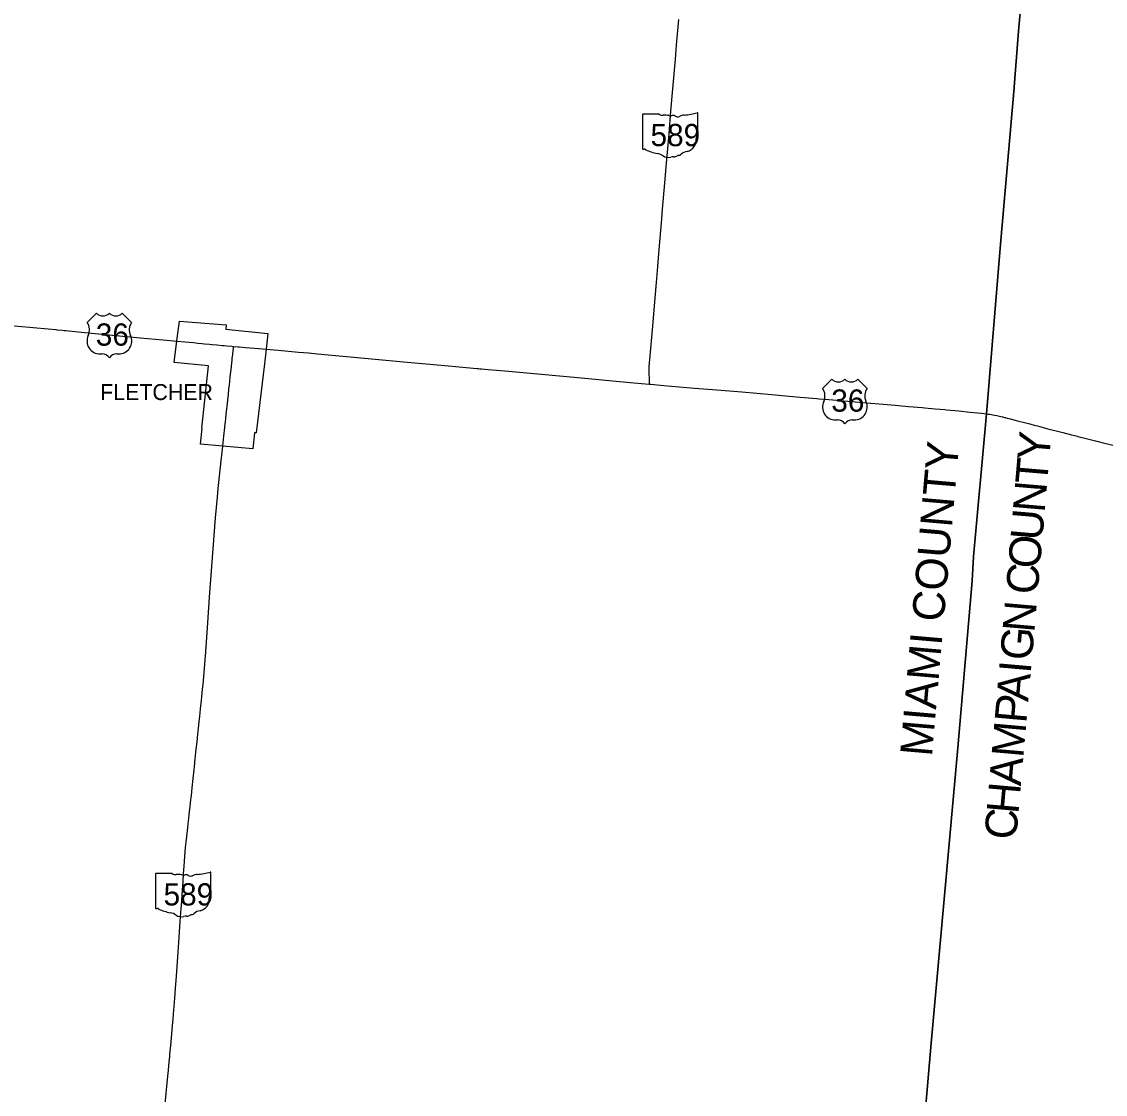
# Model space of a CAD drawing. Extents: x 0 to 34, y 0 to 22.
# Drawn here: x 5.598 to 6.143, y 17.041 to 17.581 of the extents above; entities that cross this region are included whole.
import ezdxf

# ---------------------------------------------------------------- set-up
doc = ezdxf.new("R2010")
doc.units = 0
for name, color, linetype in [('GM_X_Corporation', 7, 'Continuous'), ('GM_X_Corporation_Text', 7, 'Continuous'), ('GM_X_County', 7, 'Continuous'), ('GM_X_County_Text', 7, 'Continuous'), ('GM_X_State_Location', 7, 'Continuous'), ('GM_X_State_Route', 7, 'Continuous'), ('GM_X_State_Shield', 7, 'Continuous'), ('GM_X_US_Location', 7, 'Continuous'), ('GM_X_US_Route', 7, 'Continuous'), ('GM_X_US_Shield', 7, 'Continuous')]:
    doc.layers.add(name, color=color, linetype=linetype)

msp = doc.modelspace()

# ---------------------------------------------------------------- linework, layer by layer
at = {"layer": 'GM_X_Corporation'}
msp.add_lwpolyline([(5.700850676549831, 17.428726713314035), (5.700656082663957, 17.42652761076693), (5.721836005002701, 17.424479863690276), (5.7210201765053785, 17.416544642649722), (5.720108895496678, 17.409158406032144), (5.71590265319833, 17.374392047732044), (5.715172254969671, 17.3744505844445), (5.714276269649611, 17.36640989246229), (5.699149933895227, 17.36769823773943), (5.687913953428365, 17.368721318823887), (5.688787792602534, 17.376755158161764), (5.688580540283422, 17.376775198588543), (5.691884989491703, 17.408043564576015), (5.674607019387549, 17.40982499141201), (5.676057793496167, 17.42065648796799), (5.677288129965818, 17.43055507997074)], close=True, dxfattribs=at)
at = {"layer": 'GM_X_County'}
for points in [[(6.105406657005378, 17.639886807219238), (6.099635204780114, 17.576585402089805), (6.097431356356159, 17.546236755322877), (6.090612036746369, 17.469472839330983), (6.083568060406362, 17.384004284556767), (6.077029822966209, 17.312128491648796), (6.076320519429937, 17.299830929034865), (6.0692306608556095, 17.21568499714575), (6.055752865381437, 17.06702314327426), (6.043257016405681, 16.922665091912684)], [(6.043257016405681, 16.922665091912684), (6.055752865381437, 17.06702314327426), (6.0692306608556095, 17.21568499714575), (6.076320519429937, 17.299830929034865), (6.077029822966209, 17.312128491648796), (6.083568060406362, 17.384004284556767), (6.090612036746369, 17.469472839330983), (6.097431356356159, 17.546236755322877), (6.099635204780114, 17.576585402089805), (6.105406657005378, 17.639886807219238)]]:
    msp.add_lwpolyline(points, dxfattribs=at)
at = {"layer": 'GM_X_State_Route'}
for p, q in [((5.707579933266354, 17.417657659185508), (5.710583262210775, 17.417391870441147)), ((5.742324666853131, 17.414603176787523), (5.74691799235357, 17.414161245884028))]:
    msp.add_line(p, q, dxfattribs=at)
for points in [[(5.913807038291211, 17.39895686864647), (5.913881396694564, 17.399477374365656), (5.913944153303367, 17.400251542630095), (5.913972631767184, 17.400878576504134), (5.913959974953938, 17.401612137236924), (5.913806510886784, 17.404296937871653), (5.913774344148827, 17.405406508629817), (5.9137875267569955, 17.406411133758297), (5.9138497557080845, 17.40773059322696), (5.914282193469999, 17.413198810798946), (5.915440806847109, 17.426329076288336), (5.916977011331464, 17.44413862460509), (5.917491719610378, 17.450036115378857), (5.91811506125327, 17.458116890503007), (5.918688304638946, 17.464735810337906), (5.919180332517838, 17.470323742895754), (5.920293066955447, 17.48416172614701), (5.920362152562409, 17.48501974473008), (5.921729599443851, 17.500356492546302), (5.922553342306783, 17.510178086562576), (5.923814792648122, 17.52493948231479), (5.924765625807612, 17.536341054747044), (5.925725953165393, 17.54763715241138), (5.926969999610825, 17.562507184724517), (5.9275849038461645, 17.56954061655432), (5.927593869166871, 17.56964239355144), (5.928712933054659, 17.582573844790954)], [(5.699173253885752, 17.36768534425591), (5.699720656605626, 17.372706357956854), (5.700169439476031, 17.37705024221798), (5.700243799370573, 17.377766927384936), (5.700327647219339, 17.37857695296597), (5.700496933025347, 17.380098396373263), (5.700653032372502, 17.381504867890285), (5.700699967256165, 17.38192833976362), (5.7010395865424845, 17.385109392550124), (5.7013280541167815, 17.38780895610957), (5.701644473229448, 17.390772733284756), (5.70196088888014, 17.393612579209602), (5.702281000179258, 17.396586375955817), (5.702492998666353, 17.39847116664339), (5.702693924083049, 17.400348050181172), (5.702919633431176, 17.402453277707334), (5.703224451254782, 17.405280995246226), (5.703309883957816, 17.40611792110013), (5.703509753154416, 17.407915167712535), (5.7038578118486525, 17.411044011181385), (5.703962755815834, 17.411992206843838), (5.7041436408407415, 17.413622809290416), (5.704223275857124, 17.41434476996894), (5.70449855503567, 17.416909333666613), (5.704602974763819, 17.417903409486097)], [(5.704602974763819, 17.417903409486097), (5.7069360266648, 17.417714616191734), (5.707579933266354, 17.417657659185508)], [(5.710583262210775, 17.417391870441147), (5.715243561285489, 17.416979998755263), (5.721039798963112, 17.416499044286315)], [(5.721039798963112, 17.416499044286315), (5.727116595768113, 17.415981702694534), (5.737265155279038, 17.415042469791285), (5.742324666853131, 17.414603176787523)], [(5.74691799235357, 17.414161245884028), (5.752141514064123, 17.413658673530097), (5.7632203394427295, 17.412667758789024), (5.775805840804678, 17.411523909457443), (5.790079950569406, 17.410212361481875), (5.812725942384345, 17.4081329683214), (5.826985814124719, 17.406835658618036), (5.827646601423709, 17.40677870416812)], [(5.827646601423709, 17.40677870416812), (5.828627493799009, 17.406693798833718), (5.829464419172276, 17.406621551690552)], [(5.829464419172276, 17.406621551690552), (5.8328042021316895, 17.406333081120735), (5.841157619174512, 17.405588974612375), (5.855948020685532, 17.4042869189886), (5.870533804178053, 17.402873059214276), (5.8831936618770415, 17.401663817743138), (5.89537045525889, 17.400584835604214), (5.906141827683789, 17.39962661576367), (5.913807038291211, 17.39895686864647)], [(5.689470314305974, 17.249522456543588), (5.689642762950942, 17.25165827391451), (5.690598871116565, 17.264126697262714), (5.691658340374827, 17.278693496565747), (5.692547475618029, 17.291634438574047), (5.693166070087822, 17.300576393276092), (5.694280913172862, 17.315985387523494), (5.695422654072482, 17.33155311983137), (5.696447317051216, 17.341997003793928), (5.696871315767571, 17.346409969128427), (5.698088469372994, 17.357306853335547), (5.699173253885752, 17.36768534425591)], [(5.6702084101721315, 17.03636264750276), (5.670733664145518, 17.041926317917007), (5.671039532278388, 17.045287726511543), (5.671543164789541, 17.050376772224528), (5.671832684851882, 17.05346816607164), (5.6722271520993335, 17.0576749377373), (5.6724491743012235, 17.060144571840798), (5.672571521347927, 17.061562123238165), (5.672990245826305, 17.065918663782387), (5.673886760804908, 17.075738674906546), (5.674199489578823, 17.079364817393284), (5.674409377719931, 17.081674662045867), (5.674580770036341, 17.08367283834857), (5.675003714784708, 17.089670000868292), (5.675394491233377, 17.094823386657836), (5.675666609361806, 17.098609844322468), (5.676149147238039, 17.105501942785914), (5.6766659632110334, 17.112969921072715), (5.677013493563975, 17.117701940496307), (5.67739372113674, 17.123172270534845), (5.677702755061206, 17.12806671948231), (5.677881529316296, 17.130775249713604), (5.678314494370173, 17.136534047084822), (5.67846584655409, 17.13869095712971), (5.678679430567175, 17.14158353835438), (5.6788555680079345, 17.144161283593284), (5.67914930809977, 17.148210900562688), (5.679451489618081, 17.152416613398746), (5.679712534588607, 17.156151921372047), (5.679912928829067, 17.15878029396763), (5.68009223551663, 17.161199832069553), (5.6804582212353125, 17.1655331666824), (5.680712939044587, 17.16828863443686), (5.681000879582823, 17.171121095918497), (5.6815182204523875, 17.1756785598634), (5.681718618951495, 17.177469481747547), (5.6820466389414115, 17.18026028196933), (5.682269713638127, 17.182206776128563), (5.6827300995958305, 17.186364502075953), (5.683072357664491, 17.189629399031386), (5.683330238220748, 17.191680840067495), (5.683777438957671, 17.195639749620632), (5.684293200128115, 17.200310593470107), (5.68472616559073, 17.2046602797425), (5.684893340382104, 17.206445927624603), (5.685311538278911, 17.21016857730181), (5.6856680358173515, 17.21357428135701), (5.6858357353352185, 17.21514792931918), (5.686232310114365, 17.218805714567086), (5.686628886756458, 17.22259428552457), (5.686802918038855, 17.224325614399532), (5.68695110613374, 17.225741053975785), (5.687308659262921, 17.228936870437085), (5.687599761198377, 17.231732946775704), (5.687788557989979, 17.233456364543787), (5.688004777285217, 17.235416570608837), (5.688444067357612, 17.239681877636), (5.689023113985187, 17.245226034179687), (5.68928151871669, 17.24775842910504), (5.689470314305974, 17.249522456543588)]]:
    msp.add_lwpolyline(points, dxfattribs=at)
at = {"layer": 'GM_X_State_Shield'}
for p, q in [((5.91038465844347, 17.53451851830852), (5.91038465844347, 17.517534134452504)), ((5.918851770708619, 17.53481075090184), (5.910659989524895, 17.53481075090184)), ((5.93835666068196, 17.526346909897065), (5.93835666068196, 17.535231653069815)), ((5.938353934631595, 17.526349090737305), (5.93835666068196, 17.526346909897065)), ((5.665249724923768, 17.152175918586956), (5.665249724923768, 17.135191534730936)), ((5.673716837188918, 17.152468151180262), (5.6655250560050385, 17.152468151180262)), ((5.69322172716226, 17.144004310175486), (5.69322172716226, 17.152889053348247)), ((5.693219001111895, 17.144006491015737), (5.69322172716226, 17.144004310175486))]:
    msp.add_line(p, q, dxfattribs=at)
for centre, major_axis, ratio, start_param, end_param in [((5.910705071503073, 17.534554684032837), (0.00032405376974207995, 0), 0.7999999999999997, 1.7126933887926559, 3.283489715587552), ((5.920802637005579, 17.53678246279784), (0.0031431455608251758, 0), 0.8000000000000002, 4.042522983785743, 4.731795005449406), ((5.921844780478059, 17.525275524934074), (0.011283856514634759, 0), 0.7999999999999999, 1.4047577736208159, 1.6578580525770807), ((5.924406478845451, 17.534642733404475), (0.0009067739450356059, 0), 0.8, 3.836095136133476, 5.185414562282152), ((5.925737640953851, 17.53267966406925), (0.001885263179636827, 0), 0.8000000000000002, 0.9506229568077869, 2.0794050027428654), ((5.928170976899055, 17.53537217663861), (0.0022679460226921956, 0), 0.8, 4.0815607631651, 5.145722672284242), ((5.932176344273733, 17.529623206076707), (0.005967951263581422, 0), 0.8000000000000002, 1.6990113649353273, 2.107814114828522), ((5.928392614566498, 17.55796625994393), (0.029664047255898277, 0), 0.7999999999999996, 4.81439421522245, 5.042368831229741), ((5.938046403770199, 17.535268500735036), (0.00031139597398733, 0), 0.8000000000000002, 6.141151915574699, 7.989035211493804), ((5.930054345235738, 17.521498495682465), (0.007419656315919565, 0), 0.8000000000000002, 5.1017524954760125, 6.440017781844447), ((5.939472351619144, 17.522628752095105), (0.0021047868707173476, 0), 0.7999999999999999, 2.3877238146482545, 3.2625368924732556), ((5.938284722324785, 17.525694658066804), (0.0004819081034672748, 0), 0.8000000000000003, 1.8839779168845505, 3.671072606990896), ((5.935218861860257, 17.52457156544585), (0.00289289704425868, 0), 0.8, 5.934694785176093, 6.69594811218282), ((5.93802444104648, 17.526312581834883), (0.0003332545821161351, 0), 0.8, 5.054540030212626, 6.418171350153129), ((5.910707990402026, 17.517496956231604), (0.00032693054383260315, 0), 0.7999999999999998, 3.0012400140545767, 4.508300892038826), ((5.910757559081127, 17.519234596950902), (0.0024948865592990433, 0), 0.8, 4.6659456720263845, 4.897461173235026), ((5.911268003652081, 17.51655426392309), (0.0008996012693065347, 0), 0.8000000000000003, 0.5192071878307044, 1.6278990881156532), ((5.922625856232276, 17.53181402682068), (0.02142156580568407, 0), 0.7999999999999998, 4.195997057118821, 4.488960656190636), ((5.916239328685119, 17.509903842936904), (0.006702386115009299, 0), 0.8, 0.8235188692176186, 1.3235874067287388), ((5.92348835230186, 17.51646999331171), (0.004253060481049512, 0), 0.8000000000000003, 4.0264810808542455, 4.996735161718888), ((5.925945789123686, 17.51059780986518), (0.003494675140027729, 0), 0.7999999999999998, 1.4956620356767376, 1.9409797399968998), ((5.926256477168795, 17.51519808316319), (0.002266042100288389, 0), 0.8, 4.691043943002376, 5.507373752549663), ((5.928306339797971, 17.513553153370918), (0.000637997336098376, 0), 0.8000000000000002, 1.1475841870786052, 2.315151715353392), ((5.92803429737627, 17.515888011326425), (0.002397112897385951, 0), 0.8000000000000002, 4.93706856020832, 5.642249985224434), ((5.93318281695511, 17.51276580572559), (0.004063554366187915, 0), 0.8000000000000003, 1.6476453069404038, 2.4884337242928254), ((5.665570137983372, 17.15221208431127), (0.00032405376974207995, 0), 0.7999999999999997, 1.7126933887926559, 3.283489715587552), ((5.675667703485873, 17.154439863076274), (0.0031431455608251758, 0), 0.8000000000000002, 4.042522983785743, 4.731795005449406), ((5.676709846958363, 17.142932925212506), (0.011283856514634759, 0), 0.7999999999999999, 1.4047577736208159, 1.6578580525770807), ((5.679271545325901, 17.1523001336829), (0.0009067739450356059, 0), 0.8, 3.836095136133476, 5.185414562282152), ((5.68060270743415, 17.15033706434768), (0.001885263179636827, 0), 0.8000000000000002, 0.9506229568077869, 2.0794050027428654), ((5.683036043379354, 17.153029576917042), (0.0022679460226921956, 0), 0.8, 4.0815607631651, 5.145722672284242), ((5.687041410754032, 17.14728060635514), (0.005967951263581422, 0), 0.8000000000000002, 1.6990113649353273, 2.107814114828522), ((5.683257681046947, 17.175623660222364), (0.029664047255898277, 0), 0.7999999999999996, 4.81439421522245, 5.042368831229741), ((5.692911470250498, 17.152925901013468), (0.00031139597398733, 0), 0.8000000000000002, 6.141151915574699, 7.989035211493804), ((5.684919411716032, 17.139155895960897), (0.007419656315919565, 0), 0.8000000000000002, 5.1017524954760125, 6.440017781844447), ((5.694337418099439, 17.140286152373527), (0.0021047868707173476, 0), 0.7999999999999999, 2.3877238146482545, 3.2625368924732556), ((5.69314978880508, 17.14335205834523), (0.0004819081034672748, 0), 0.8000000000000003, 1.8839779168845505, 3.671072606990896), ((5.690083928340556, 17.142228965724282), (0.00289289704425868, 0), 0.8, 5.934694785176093, 6.69594811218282), ((5.6928895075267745, 17.143969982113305), (0.0003332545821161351, 0), 0.8, 5.054540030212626, 6.418171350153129), ((5.665573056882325, 17.135154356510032), (0.00032693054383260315, 0), 0.7999999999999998, 3.0012400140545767, 4.508300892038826), ((5.665622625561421, 17.136891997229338), (0.0024948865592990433, 0), 0.8, 4.6659456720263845, 4.897461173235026), ((5.666133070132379, 17.134211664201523), (0.0008996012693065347, 0), 0.8000000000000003, 0.5192071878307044, 1.6278990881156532), ((5.677490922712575, 17.149471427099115), (0.02142156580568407, 0), 0.7999999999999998, 4.195997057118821, 4.488960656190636), ((5.671104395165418, 17.127561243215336), (0.006702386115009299, 0), 0.8, 0.8235188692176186, 1.3235874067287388), ((5.67835341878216, 17.134127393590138), (0.004253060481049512, 0), 0.8000000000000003, 4.0264810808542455, 4.996735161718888), ((5.680810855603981, 17.128255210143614), (0.003494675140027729, 0), 0.7999999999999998, 1.4956620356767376, 1.9409797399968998), ((5.681121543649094, 17.132855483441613), (0.002266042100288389, 0), 0.8, 4.691043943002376, 5.507373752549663), ((5.68317140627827, 17.131210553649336), (0.000637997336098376, 0), 0.8000000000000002, 1.1475841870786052, 2.315151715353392), ((5.682899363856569, 17.13354541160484), (0.002397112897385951, 0), 0.8000000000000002, 4.93706856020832, 5.642249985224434), ((5.688047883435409, 17.13042320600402), (0.004063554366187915, 0), 0.8000000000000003, 1.6476453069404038, 2.4884337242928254)]:
    msp.add_ellipse(centre, major_axis=major_axis, ratio=ratio, start_param=start_param, end_param=end_param, dxfattribs=at)
at = {"layer": 'GM_X_US_Route'}
for p, q in [((5.707579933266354, 17.417657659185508), (5.710583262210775, 17.417391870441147)), ((5.742324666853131, 17.414603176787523), (5.74691799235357, 17.414161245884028))]:
    msp.add_line(p, q, dxfattribs=at)
for points in [[(5.576346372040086, 17.43001217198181), (5.578377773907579, 17.429827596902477), (5.596147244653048, 17.428153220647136), (5.611258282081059, 17.426698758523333), (5.615061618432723, 17.426345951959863)], [(5.615061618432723, 17.426345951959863), (5.615632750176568, 17.426291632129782), (5.618269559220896, 17.42603322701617), (5.619274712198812, 17.425934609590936)], [(5.619274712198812, 17.425934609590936), (5.620228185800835, 17.42584074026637), (5.629624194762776, 17.42495107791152), (5.641899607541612, 17.423768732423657), (5.657586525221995, 17.422282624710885), (5.669149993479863, 17.421237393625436), (5.676025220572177, 17.420615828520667)], [(5.676025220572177, 17.420615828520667), (5.676109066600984, 17.420608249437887), (5.684344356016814, 17.419802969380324), (5.686535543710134, 17.419592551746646), (5.688616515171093, 17.419393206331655), (5.690020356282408, 17.41925714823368), (5.69252005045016, 17.419015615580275), (5.693758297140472, 17.41889590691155), (5.696206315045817, 17.41867230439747), (5.698961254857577, 17.418420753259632), (5.699875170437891, 17.418336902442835), (5.701170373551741, 17.41821982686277), (5.7037090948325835, 17.41798989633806), (5.704602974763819, 17.417903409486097)], [(5.704602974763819, 17.417903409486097), (5.7069360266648, 17.417714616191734), (5.707579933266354, 17.417657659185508)], [(5.710583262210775, 17.417391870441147), (5.715243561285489, 17.416979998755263), (5.721039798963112, 17.416499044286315)], [(5.721039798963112, 17.416499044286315), (5.727116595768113, 17.415981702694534), (5.737265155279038, 17.415042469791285), (5.742324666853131, 17.414603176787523)], [(5.74691799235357, 17.414161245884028), (5.752141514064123, 17.413658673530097), (5.7632203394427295, 17.412667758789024), (5.775805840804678, 17.411523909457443), (5.790079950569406, 17.410212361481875), (5.812725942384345, 17.4081329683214), (5.826985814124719, 17.406835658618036), (5.827646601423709, 17.40677870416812)], [(5.827646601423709, 17.40677870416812), (5.828627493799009, 17.406693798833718), (5.829464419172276, 17.406621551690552)], [(5.829464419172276, 17.406621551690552), (5.8328042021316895, 17.406333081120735), (5.841157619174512, 17.405588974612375), (5.855948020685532, 17.4042869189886), (5.870533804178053, 17.402873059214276), (5.8831936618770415, 17.401663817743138), (5.89537045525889, 17.400584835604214), (5.906141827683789, 17.39962661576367), (5.913807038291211, 17.39895686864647)], [(5.913807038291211, 17.39895686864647), (5.914569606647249, 17.39887301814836), (5.921254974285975, 17.398266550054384), (5.936700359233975, 17.396960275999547), (5.947797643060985, 17.395993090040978), (5.96039316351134, 17.39496948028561), (5.975527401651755, 17.393667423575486), (5.987769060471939, 17.392597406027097), (5.998131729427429, 17.39168612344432), (5.9992207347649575, 17.391588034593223), (6.002475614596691, 17.391295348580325), (6.0212845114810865, 17.38968584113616), (6.037665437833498, 17.388271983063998), (6.044288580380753, 17.387676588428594), (6.051157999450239, 17.38706906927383), (6.052569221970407, 17.3869572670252), (6.057702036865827, 17.386551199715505), (6.060267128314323, 17.386323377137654), (6.0626112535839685, 17.386115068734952), (6.063515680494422, 17.38602489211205), (6.069620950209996, 17.38541684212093), (6.075227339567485, 17.3848583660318), (6.081068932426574, 17.38427246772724), (6.083587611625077, 17.383958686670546)], [(6.083587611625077, 17.383958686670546), (6.083998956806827, 17.383903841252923), (6.084618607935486, 17.383810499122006), (6.085211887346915, 17.383713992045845), (6.086095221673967, 17.38356316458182), (6.086768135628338, 17.383441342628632), (6.087701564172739, 17.3832752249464), (6.088735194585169, 17.383070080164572), (6.089507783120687, 17.382907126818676), (6.0902318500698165, 17.382767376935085), (6.090895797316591, 17.38260653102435), (6.091513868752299, 17.382477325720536), (6.091870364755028, 17.38238556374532), (6.09263556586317, 17.382191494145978), (6.093195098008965, 17.38204172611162), (6.094014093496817, 17.381838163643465), (6.094800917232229, 17.381637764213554), (6.095651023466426, 17.38143789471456), (6.098607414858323, 17.38066161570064), (6.100544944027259, 17.380150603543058), (6.102073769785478, 17.379745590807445), (6.104060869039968, 17.37921453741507), (6.1054879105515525, 17.378835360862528), (6.107577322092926, 17.378281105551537), (6.10920528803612, 17.37783495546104), (6.11155363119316, 17.37722901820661), (6.11445676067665, 17.376450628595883), (6.1157862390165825, 17.376112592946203), (6.117213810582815, 17.37573921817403), (6.118080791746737, 17.375511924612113), (6.119406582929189, 17.375164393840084), (6.121959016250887, 17.37450097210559), (6.126461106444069, 17.3733708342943), (6.128779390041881, 17.372793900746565), (6.1296331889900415, 17.372581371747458), (6.13448755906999, 17.371341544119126), (6.137143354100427, 17.370665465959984), (6.138523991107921, 17.370318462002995), (6.142415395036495, 17.36936182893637), (6.149318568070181, 17.367618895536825)]]:
    msp.add_lwpolyline(points, dxfattribs=at)
at = {"layer": 'GM_X_US_Shield'}
for p, q in [((5.635529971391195, 17.43460672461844), (5.630867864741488, 17.42994461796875)), ((5.653245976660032, 17.42994461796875), (5.648583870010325, 17.43460672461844)), ((5.637394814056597, 17.414093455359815), (5.6383272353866, 17.414093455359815)), ((5.645786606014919, 17.414093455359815), (5.646719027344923, 17.414093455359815)), ((6.005778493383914, 17.401365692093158), (6.001116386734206, 17.396703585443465)), ((6.0234944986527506, 17.396703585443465), (6.018832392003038, 17.401365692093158)), ((6.007643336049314, 17.380852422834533), (6.008575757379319, 17.380852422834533)), ((6.016035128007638, 17.380852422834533), (6.016967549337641, 17.380852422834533))]:
    msp.add_line(p, q, dxfattribs=at)
for centre, radius, start, end in [((5.63879344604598, 17.437936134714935), 0.004662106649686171, 225.57299599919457, 314.4270040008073), ((5.645320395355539, 17.437936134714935), 0.004662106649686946, 225.57299599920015, 314.4270040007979), ((5.625521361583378, 17.426200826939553), 0.006526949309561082, 334.5471236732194, 35.000929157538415), ((5.658592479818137, 17.426200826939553), 0.006526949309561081, 144.99907084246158, 205.4528763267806), ((5.637322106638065, 17.420619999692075), 0.006526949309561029, 154.8319194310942, 270.63826363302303), ((5.64679173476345, 17.420619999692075), 0.006526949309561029, 269.36173636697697, 25.168080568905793), ((5.638327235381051, 17.409431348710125), 0.0046621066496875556, 36.86989764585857, 89.99999993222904), ((5.645786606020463, 17.409431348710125), 0.0046621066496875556, 90.00000006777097, 143.13010235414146), ((5.995769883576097, 17.39295979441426), 0.006526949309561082, 334.5471236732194, 35.000929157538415), ((6.0090419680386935, 17.404695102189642), 0.004662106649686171, 225.57299599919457, 314.4270040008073), ((6.015568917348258, 17.404695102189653), 0.004662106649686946, 225.57299599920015, 314.4270040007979), ((6.028841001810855, 17.39295979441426), 0.006526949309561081, 144.99907084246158, 205.4528763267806), ((6.007570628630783, 17.387378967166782), 0.006526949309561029, 154.8319194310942, 270.63826363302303), ((6.017040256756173, 17.387378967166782), 0.006526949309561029, 269.36173636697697, 25.168080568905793), ((6.0085757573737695, 17.37619031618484), 0.0046621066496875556, 36.86989764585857, 89.99999993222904), ((6.016035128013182, 17.37619031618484), 0.0046621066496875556, 90.00000006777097, 143.13010235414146)]:
    msp.add_arc(centre, radius, start, end, dxfattribs=at)

# ---------------------------------------------------------------- texts
at = {"layer": 'GM_X_Corporation_Text'}
msp.add_text('FLETCHER', height=0.008037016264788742, rotation=1.0000000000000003e-05, dxfattribs=at).set_placement((5.637459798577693, 17.390886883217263))
at = {"layer": 'GM_X_County_Text'}
for s, height, rotation, p in [('Y', 0.016074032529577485, 85.108582, (6.115090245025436, 17.360005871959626)), ('MIAMI COUNTY', 0.016074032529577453, 85.017319, (6.056118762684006, 17.211064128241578)), ('T', 0.016074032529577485, 85.108582, (6.1140670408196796, 17.348049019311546)), ('N', 0.016074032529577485, 85.10849, (6.112857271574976, 17.333913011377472)), ('U', 0.016074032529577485, 85.10849, (6.111647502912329, 17.319777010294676)), ('O', 0.016074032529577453, 85.108467, (6.110437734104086, 17.305641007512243)), ('C', 0.016074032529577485, 85.073647, (6.10931151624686, 17.292575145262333)), ('N', 0.016074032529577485, 85.013191, (6.107650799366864, 17.27352950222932)), ('G', 0.016074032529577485, 84.99395, (6.106412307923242, 17.259390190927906)), ('I', 0.016074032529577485, 84.988831, (6.105840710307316, 17.25287125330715)), ('A', 0.016074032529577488, 84.985397, (6.104600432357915, 17.238736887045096)), ('P', 0.016074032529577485, 84.983681, (6.1036450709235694, 17.227852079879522)), ('M', 0.016074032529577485, 84.983315, (6.1021174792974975, 17.210448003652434)), ('A', 0.016074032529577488, 84.983177, (6.1008768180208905, 17.19631442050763)), ('H', 0.016074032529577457, 84.983246, (6.099636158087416, 17.182181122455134)), ('C', 0.016074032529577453, 84.9832, (6.098490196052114, 17.169127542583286))]:
    msp.add_text(s, height=height, rotation=rotation, dxfattribs=at).set_placement(p)
at = {"layer": 'GM_X_State_Location'}
for p in [(5.918381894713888, 17.523727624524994), (5.673246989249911, 17.14138514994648)]:
    msp.add_text('589', height=1.6074032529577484e-05, rotation=1.0000000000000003e-05, dxfattribs=at).set_placement(p)
for s, p in [('s', (5.924056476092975, 17.524897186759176)), ('r', (5.924055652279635, 17.524897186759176)), ('s', (5.678921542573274, 17.142554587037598)), ('r', (5.678920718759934, 17.142554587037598))]:
    msp.add_text(s, height=1.6074032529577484e-05, dxfattribs=at).set_placement(p)
at = {"layer": 'GM_X_State_Shield'}
for p in [(5.914498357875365, 17.51873182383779), (5.669363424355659, 17.136389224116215)]:
    msp.add_text('589', height=0.011189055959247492, dxfattribs=at).set_placement(p)
at = {"layer": 'GM_X_US_Location'}
for s, p in [('0', (5.642050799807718, 17.423795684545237)), ('/', (5.642052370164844, 17.423795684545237)), ('0', (6.012299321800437, 17.39055465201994)), ('/', (6.012300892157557, 17.39055465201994))]:
    msp.add_text(s, height=1.6074032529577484e-05, dxfattribs=at).set_placement(p)
for p in [(5.638732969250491, 17.420468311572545), (6.008981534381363, 17.38722719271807)]:
    msp.add_text('36', height=1.6074032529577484e-05, rotation=1.0000000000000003e-05, dxfattribs=at).set_placement(p)
at = {"layer": 'GM_X_US_Shield'}
for p in [(5.635232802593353, 17.418289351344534), (6.005481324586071, 17.38504831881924)]:
    msp.add_text('36', height=0.011189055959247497, dxfattribs=at).set_placement(p)

doc.saveas('drawing.dxf')
